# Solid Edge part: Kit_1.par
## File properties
Dokumentum tartalom típus: 0
Last saved by: ahadarics
Revision: 77
Sűrűség: 0,000 kg/m^3
Pontosság: 0,990
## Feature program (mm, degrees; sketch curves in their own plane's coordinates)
base feature "unnamed BaseFeature 1"
sketch for "unnamed Hole 1" plane through (-19, 19, 90) normal (0, 0, 1) x-axis (0, 1, 0)
hole "unnamed Hole 1" through
sketch for "unnamed Hole 2" plane through (-19, 19, 90) normal (0, 0, 1) x-axis (0, 1, 0)
  hole centre (-38, 0) bore radius 2.4585
hole "unnamed Hole 2" through
sketch for "unnamed Hole 3" plane through (-19, 19, 90) normal (0, 0, 1) x-axis (0, 1, 0)
  hole centre (0, -38) bore radius 2.4585
hole "unnamed Hole 3" through
sketch for "unnamed Hole 4" plane through (-19, 19, 90) normal (0, 0, 1) x-axis (0, 1, 0)
  hole centre (-38, -38) bore radius 2.4585
hole "unnamed Hole 4" through
pattern "unnamed Pattern 1" of "unnamed Hole 1", "unnamed Hole 2", "unnamed Hole 3", "unnamed Hole 4"
sketch for "Furat_5" plane through (-26.4337, -0.0028, 86.9955) normal (-0.999944, 0, 0.01058) x-axis (-0.01058, 0, -0.999944)
  hole centre (0.0048, -0.0027) bore radius 4.283
hole "Furat_5" diameter 8.566 finite
thread "unnamed Thread 1"
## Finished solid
Body 1: solid body, 305 faces, 703 edges, 418 vertices, 4 internal voids.
  Faces by surface: plane 147, cylinder 74, swept 43, torus 22, cone 18, spline 1
  Edges by curve: line 415, circle 174, spline 98, ellipse 12, curve on surface 4
Bounding box of the edges (mm; curved faces can reach further): 54.800 x 54.800 x 14.500, from (-27.4, -27.4, 80.5) to (27.4, 27.4, 95).
Cylindrical faces by radius (mm): R0.2 x36, R0.519 x1, R2.4585 x4, R2.5402 x12, R2.6 x4, R3.75 x4, R3.85 x4, R4.283 x1, R4.5 x4, R6.27 x1, R6.85 x1, R7 x1, R8.25 x1
Conical faces (half-angle, radius in mm at the cone's reference point): 0.5 deg R6.75 x4, 7 deg R7.5925 x1, 14 deg R6.135 x1, 14 deg R6.4811 x1, 17 deg R6.135 x1, 23 deg R6.829 x1, 42.5 deg R6.1233 x1, 45 deg R2.7085 x4, 45 deg R7 x1, 84 deg R6.4608 x1, 85 deg R7.9463 x1, 87 deg R6.1765 x1
Toroidal faces (ring radius, tube radius in mm): R2.9402 r0.4 x12, R3.55 r0.2 x8, R6.8057 r0.2025 x1, R7.2522 r0.2925 x1
Planar faces by outward normal: +x 13, +y 14, +z 24, -x 14, -y 15, -z 1, oblique 66
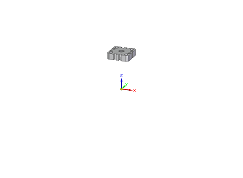
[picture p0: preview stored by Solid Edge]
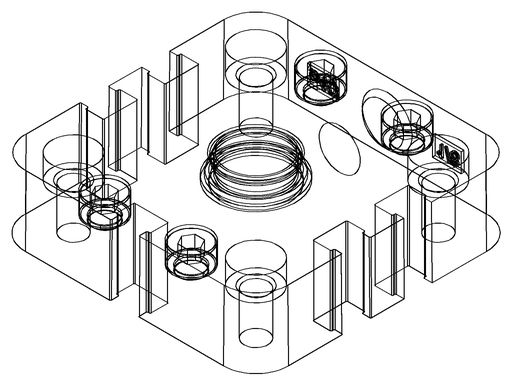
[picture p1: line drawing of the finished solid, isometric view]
